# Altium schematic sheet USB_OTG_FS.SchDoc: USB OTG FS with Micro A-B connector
size A4; Date: 25-FEB-2015; Author: A.B; CompanyName: STMicroelectronics; Address1: 12, Rue Jules HOROWITZ; Address2: 38019 Grenoble; Address3: FRANCE; DocumentNumber: MB1191; Revision: B-02; SheetNumber: 9; SheetTotal: 14; Project: STM32F746G-DISCO
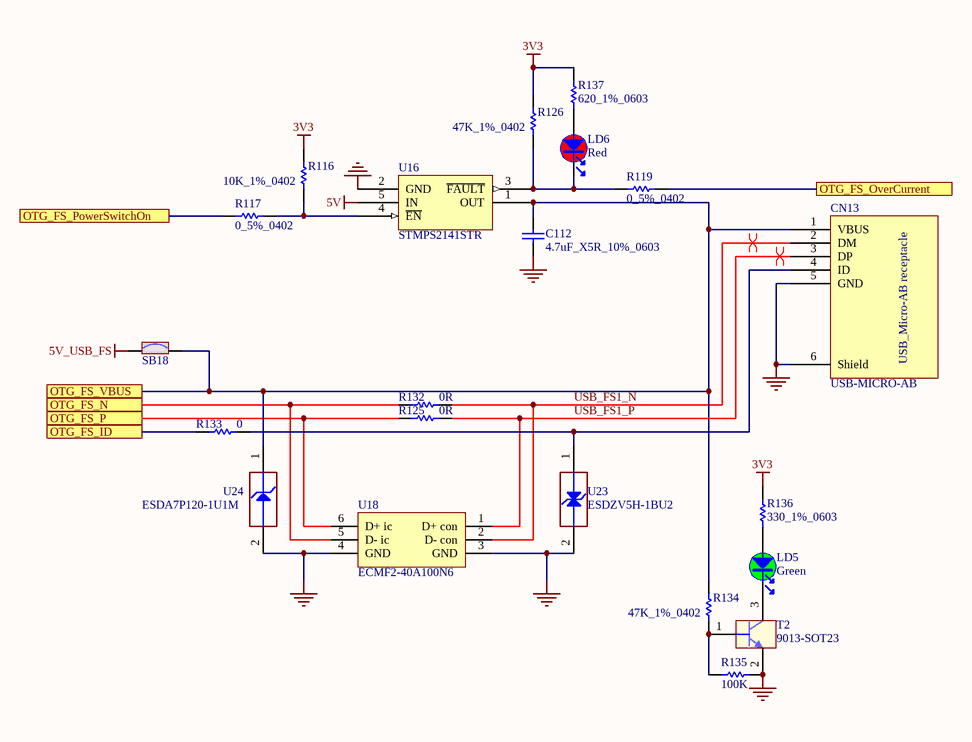
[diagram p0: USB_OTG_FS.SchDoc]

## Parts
C112  4.7uF_X5R_10%_0603  [0603C]
CN13  USB-MICRO-AB  [USB-MICRO-AB]
LD5  Green  [LED_0603_GREEN]
LD6  Red  [LED_0603_VISHAY_VLMS1300-GS08_RED_1A2K_H0P8]
R116  10K_1%_0402  [0402R]
R117  0_5%_0402  [0402R]
R119  0_5%_0402  [0402R]
R125  0R  [0402R]
R126  47K_1%_0402  [0402R]
R132  0R  [0402R]
R133  0  [0402R]
R134  47K_1%_0402  [0402R]
R135  100K  [0402R]
R136  330_1%_0603  [0603R]
R137  620_1%_0603  [0603R]
SB18  Solder Bridge ON  [JP2_SMD]  (value not drawn)
T2  9013-SOT23  [SOT23]
U16  STMPS2141STR  [SOT23-5L]
U18  ECMF2-40A100N6  [ESD_UQFN-6L_1P45X1P4_P040]
U23  ESDZV5H-1BU2  [ESD-BI_ST0201_H0P24]
U24  ESDA7P120-1U1M  [ESD_QFN1610_2N_1K_2A]

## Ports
OTG_FS_ID, OTG_FS_N, OTG_FS_OverCurrent, OTG_FS_P, OTG_FS_PowerSwitchOn, OTG_FS_VBUS

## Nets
3V3: R116.2 R126.2 R136.2 R137.2
5V: U16.5(IN)
5V_USB_FS: SB18.1
GND: C112.1 CN13.5(GND) CN13.6(Shield) R135.2 T2.2(E) U16.2(GND) U18.3(GND) U18.4(GND) U23.2(GND) U24.2(GND)
OTG_FS_ID: R133.1 ; port OTG_FS_ID
OTG_FS_N: R132.1 U18.5(D-_ic) ; port OTG_FS_N
OTG_FS_OverCurrent: R119.2 ; port OTG_FS_OverCurrent
OTG_FS_P: R125.1 U18.6(D+_ic) ; port OTG_FS_P
OTG_FS_PowerSwitchOn: R117.1 ; port OTG_FS_PowerSwitchOn
OTG_FS_VBUS: C112.2 CN13.1(VBUS) R134.2 SB18.2 U16.1(OUT) U24.1(IO1) ; port OTG_FS_VBUS
USB_FS1_N: CN13.2(DM) R132.2 U18.2(D-_con)
USB_FS1_P: CN13.3(DP) R125.2 U18.1(D+_con)
NetCN13_4: CN13.4(ID) R133.2 U23.1(IO1)
NetLD5_1: LD5.1 R136.1
NetLD5_2: LD5.2 T2.3(C)
NetLD6_1: LD6.1 R137.1
NetLD6_2: LD6.2 R119.1 R126.1 U16.3(~{FAULT})
NetR116_1: R116.1 R117.2 U16.4(~{EN})
NetR134_1: R134.1 R135.1 T2.1(B)

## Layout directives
differential pair: USB_FS1_N, USB_FS1_P

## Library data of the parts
C112 = Cap_4.7uF_X5R_10%_0603: Capacitor,4.7uF,16V, X5R,10%,0603,YAGEO; Manuf_Part_1: CC0603KRX5R7BB475; Order: CC0603KRX5R7BB105
CN13 = USB-MICRO-AB: USB-MICRO-AB, 47590-0001, SMT, MOLEX; Ref St: xxxxxxx
LD5 = LED_green: LED, Green, 2V, 20mA, 0603
LD6 = Red: LED, Red, 1V7 to 2V2, 5mA, 0603
R116 = Res_10K_1%_0402: Resistor,10K,0402,1%,YAGEO; Manuf_Part_1: RC0402FR-0710KL
R117 R119 = Res_0_5%_0402: Resistor,0,0402,5%,YAGEO; Manuf_Part_1: RC0402JR-070RL; Value: 0; Order: 2363467
R125 R132 = Res_0_5%_0402: Resistor, 0R, 0402, +/-5%, 1/16W; Manuf_Part_1: RC0402JR-070RL; Manuf_1: YAGEO; Value: 0; Order: 2363467
R126 R134 = Res_47K_1%_0402: Resistor,47K,0402,1%,YAGEO; Manuf_Part_1: RC0402FR-0747KL; Order: 9239430
R133 = Res_0_5%_0402: Resistor,0,0402,5%,YAGEO; Manuf_Part_1: RC0402JR-070RL; Order: 2363467
R135 = Res_100K_1%_0402: Resistor,100K,0402,1%,YAGEO; Manuf_Part_1: RT0402FRE07100KL
R136 = Res_330_1%_0603: Resistor,330,0603,1%,YAGEO; Manuf_Part_1: RT0603FRE07330RL; Value: 330; Order: 1500622RL
R137 = Res_620_1%_0603: Resistor,620,0603,1%,VISHAY; Manuf_Part_1: CRCW0603620RFKEA; Manuf_1: VISHAY DRALORIC; Value: 620; Order: 2122341
SB18 = SB_ON: Solder: YES
T2 = 9013-SOT23: NPN Bipolar Transistor; Manuf_1: NXP; Manuf_Part_1: BSR14; Order: 1081310; ECCN_US/EU: EAR99/NEC
U16 = STMPS2141STR: Enhanced single channel power switches; Manuf_1: STM; Provided: ST; ECCN_US/EU: EAR99/NEC; Ref St: 9159003
U18 = ECMF2-40A100N6: / IC, ESD protection and Common Filter High Speed serial Interfaces, 10.7 GHz
U23 = ESDZV5H-1BU2: Diode, ESD TVS, 5V5, 50nA, 10V, 0201
U24 = ESDA7P120-1U1M: Diode, ESD TVS, 5V5, 1.5uA, 6V8, QFN1610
